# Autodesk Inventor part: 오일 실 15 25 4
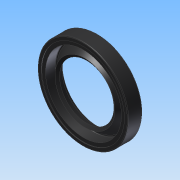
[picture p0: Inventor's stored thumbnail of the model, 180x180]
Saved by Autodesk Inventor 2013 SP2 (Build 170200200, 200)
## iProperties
Created: 2025-10
Part Number: 오일 실 15 25 4
Material: Generic
Document SubType Name: Modeling
Designer: a
Density: 1 g/cm^3
Author: a
변환 표준: STEP AP214IS
전처리기: Build: 200, Release: 2013 SP2 Update 6 - Date: Thu 07/17/2014
전송 단위: 밀리미터
불확실성: 0.01
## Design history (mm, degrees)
node "오일 실 15 25 41"
body "Solid1"
node "기준1"
